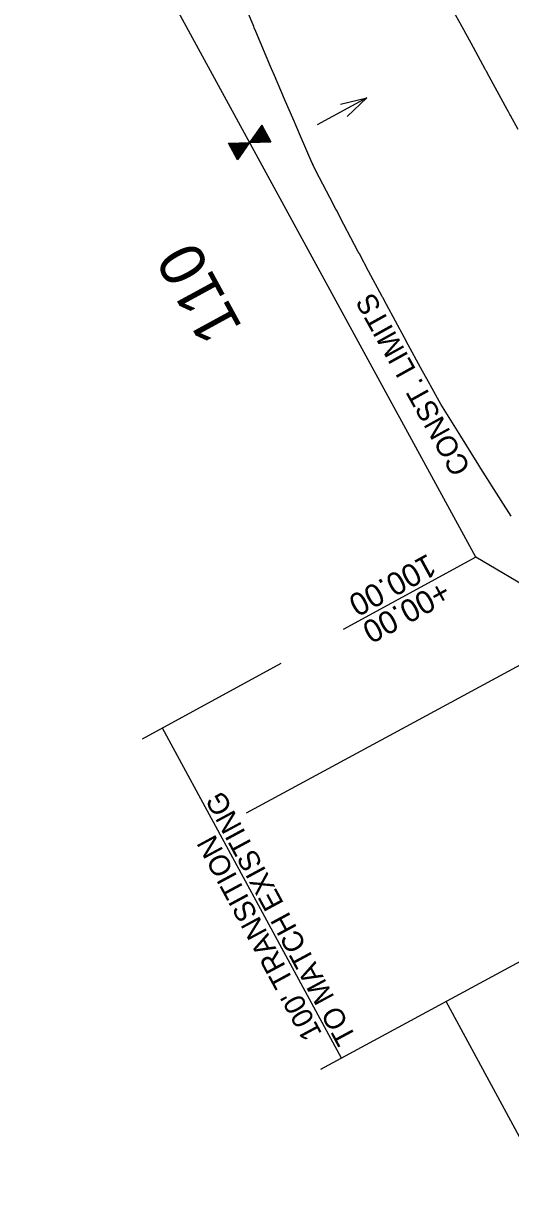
# Model space of a CAD drawing. Extents: x 1627557 to 1636561, y 783843 to 794002.
# Drawn here: x 1628014.2 to 1628143.1, y 784399.8 to 784710.3 of the extents above; entities that cross this region are included whole.
import ezdxf

# ---------------------------------------------------------------- set-up
doc = ezdxf.new("R2010")
doc.units = 0
for name, color, linetype in [('Flow Arrows', 7, 'Continuous'), ('GATE', 7, 'Continuous'), ('R_Clearzone', 7, 'Continuous'), ('R_Ditch', 7, 'Continuous'), ('R_Horz Alg Annot', 7, 'Continuous'), ('R_Proposed Const Limits', 7, 'Continuous'), ('R_Proposed Const Limits Annot', 7, 'Continuous'), ('R_ROW', 7, 'Continuous'), ('R_ROW Annot', 7, 'Continuous'), ('Transition Dimensions', 7, 'Continuous')]:
    doc.layers.add(name, color=color, linetype=linetype)

msp = doc.modelspace()

# ---------------------------------------------------------------- linework, layer by layer
at = {"layer": 'Flow Arrows'}
msp.add_line((1628105.06, 784690.6), (1628091.89, 784683.42), dxfattribs=at)
msp.add_lwpolyline([(1628098.06, 784688.91), (1628105.06, 784690.6), (1628099.84, 784685.63)], dxfattribs=at)
at = {"layer": 'GATE'}
for p, q in [((1628076.28, 784681.97), (1628077.95, 784678.91)), ((1628076.35, 784682.06), (1628078.06, 784678.91)), ((1628076.41, 784682.15), (1628078.17, 784678.92)), ((1628076.47, 784682.24), (1628078.29, 784678.92)), ((1628076.54, 784682.34), (1628078.4, 784678.92)), ((1628076.6, 784682.43), (1628078.51, 784678.93)), ((1628076.66, 784682.52), (1628078.62, 784678.93)), ((1628076.73, 784682.61), (1628078.73, 784678.94)), ((1628076.79, 784682.7), (1628078.84, 784678.94)), ((1628076.86, 784682.8), (1628078.96, 784678.94)), ((1628076.92, 784682.89), (1628079.07, 784678.95)), ((1628076.98, 784682.98), (1628079.18, 784678.95)), ((1628077.05, 784683.07), (1628079.29, 784678.96)), ((1628077.11, 784683.16), (1628079.4, 784678.96)), ((1628077.18, 784683.25), (1628079.51, 784678.96)), ((1628077.24, 784683.35), (1628079.63, 784678.97)), ((1628074.11, 784678.85), (1628074.15, 784678.77)), ((1628074.17, 784678.94), (1628074.26, 784678.78)), ((1628074.24, 784679.03), (1628074.38, 784678.78)), ((1628074.3, 784679.12), (1628074.49, 784678.79)), ((1628074.37, 784679.22), (1628074.6, 784678.79)), ((1628074.43, 784679.31), (1628074.71, 784678.79)), ((1628074.49, 784679.4), (1628074.82, 784678.8)), ((1628074.56, 784679.49), (1628074.93, 784678.8)), ((1628074.62, 784679.58), (1628075.05, 784678.81)), ((1628074.69, 784679.68), (1628075.16, 784678.81)), ((1628074.75, 784679.77), (1628075.27, 784678.81)), ((1628074.81, 784679.86), (1628075.38, 784678.82)), ((1628074.88, 784679.95), (1628075.49, 784678.82)), ((1628074.94, 784680.04), (1628075.6, 784678.83)), ((1628075, 784680.13), (1628075.72, 784678.83)), ((1628075.07, 784680.23), (1628075.83, 784678.83)), ((1628075.13, 784680.32), (1628075.94, 784678.84)), ((1628075.2, 784680.41), (1628076.05, 784678.84)), ((1628075.26, 784680.5), (1628076.16, 784678.85)), ((1628075.32, 784680.59), (1628076.27, 784678.85)), ((1628075.39, 784680.68), (1628076.39, 784678.85)), ((1628075.45, 784680.78), (1628076.5, 784678.86)), ((1628075.52, 784680.87), (1628076.61, 784678.86)), ((1628075.58, 784680.96), (1628076.72, 784678.87)), ((1628075.64, 784681.05), (1628076.83, 784678.87)), ((1628075.71, 784681.14), (1628076.94, 784678.87)), ((1628075.77, 784681.24), (1628077.06, 784678.88)), ((1628075.83, 784681.33), (1628077.17, 784678.88)), ((1628075.9, 784681.42), (1628077.28, 784678.89)), ((1628075.96, 784681.51), (1628077.39, 784678.89)), ((1628076.03, 784681.6), (1628077.5, 784678.89)), ((1628076.09, 784681.69), (1628077.62, 784678.9)), ((1628076.15, 784681.79), (1628077.73, 784678.9)), ((1628076.22, 784681.88), (1628077.84, 784678.9)), ((1628068.55, 784678.57), (1628070.91, 784674.25)), ((1628068.66, 784678.58), (1628070.97, 784674.34)), ((1628068.77, 784678.58), (1628071.04, 784674.43)), ((1628068.88, 784678.59), (1628071.1, 784674.52)), ((1628069, 784678.59), (1628071.16, 784674.61)), ((1628069.11, 784678.59), (1628071.23, 784674.71)), ((1628069.22, 784678.6), (1628071.29, 784674.8)), ((1628069.33, 784678.6), (1628071.36, 784674.89)), ((1628069.44, 784678.61), (1628071.42, 784674.98)), ((1628069.55, 784678.61), (1628071.48, 784675.07)), ((1628069.67, 784678.61), (1628071.55, 784675.17)), ((1628069.78, 784678.62), (1628071.61, 784675.26)), ((1628069.89, 784678.62), (1628071.67, 784675.35)), ((1628070, 784678.63), (1628071.74, 784675.44)), ((1628070.11, 784678.63), (1628071.8, 784675.53)), ((1628070.22, 784678.63), (1628071.87, 784675.62)), ((1628070.34, 784678.64), (1628071.93, 784675.72)), ((1628070.45, 784678.64), (1628071.99, 784675.81)), ((1628070.56, 784678.65), (1628072.06, 784675.9)), ((1628070.67, 784678.65), (1628072.12, 784675.99)), ((1628070.78, 784678.65), (1628072.19, 784676.08)), ((1628070.9, 784678.66), (1628072.25, 784676.17)), ((1628071.01, 784678.66), (1628072.31, 784676.27)), ((1628071.12, 784678.67), (1628072.38, 784676.36)), ((1628071.23, 784678.67), (1628072.44, 784676.45)), ((1628071.34, 784678.67), (1628072.5, 784676.54)), ((1628071.45, 784678.68), (1628072.57, 784676.63)), ((1628071.57, 784678.68), (1628072.63, 784676.73)), ((1628071.68, 784678.69), (1628072.7, 784676.82)), ((1628071.79, 784678.69), (1628072.76, 784676.91)), ((1628071.9, 784678.69), (1628072.82, 784677)), ((1628072.01, 784678.7), (1628072.89, 784677.09)), ((1628072.12, 784678.7), (1628072.95, 784677.18)), ((1628072.24, 784678.71), (1628073.02, 784677.28)), ((1628072.35, 784678.71), (1628073.08, 784677.37)), ((1628072.46, 784678.71), (1628073.14, 784677.46)), ((1628072.57, 784678.72), (1628073.21, 784677.55)), ((1628072.68, 784678.72), (1628073.27, 784677.64)), ((1628072.79, 784678.73), (1628073.34, 784677.73)), ((1628072.91, 784678.73), (1628073.4, 784677.83)), ((1628073.02, 784678.73), (1628073.46, 784677.92)), ((1628073.13, 784678.74), (1628073.53, 784678.01)), ((1628073.24, 784678.74), (1628073.59, 784678.1)), ((1628073.35, 784678.75), (1628073.65, 784678.19)), ((1628073.47, 784678.75), (1628073.72, 784678.29)), ((1628073.58, 784678.75), (1628073.78, 784678.38)), ((1628073.69, 784678.76), (1628073.85, 784678.47)), ((1628073.8, 784678.76), (1628073.91, 784678.56)), ((1628073.91, 784678.77), (1628073.97, 784678.65)), ((1628074.02, 784678.77), (1628074.04, 784678.74))]:
    msp.add_line(p, q, dxfattribs=at)
for points in [[(1628077.25, 784683.36), (1628074.06, 784678.77), (1628079.64, 784678.97)], [(1628068.47, 784678.57), (1628074.06, 784678.77), (1628070.86, 784674.18)]]:
    msp.add_lwpolyline(points, close=True, dxfattribs=at)
at = {"layer": 'R_Clearzone'}
msp.add_lwpolyline([(1628145.09, 784682.19), (1628143.05, 784685.93), (1628142.9, 784686.19), (1628142.55, 784686.85), (1628142.21, 784687.46), (1628137.43, 784696.24), (1628136.63, 784697.7), (1628136.58, 784697.8), (1628136.35, 784698.21), (1628132.64, 784705.02), (1628130.25, 784709.4), (1628130.21, 784709.47), (1628130.16, 784709.57), (1628127.85, 784713.8)], dxfattribs=at)
at = {"layer": 'R_Ditch'}
msp.add_lwpolyline([(1628145.09, 784682.19), (1628143.05, 784685.93), (1628142.9, 784686.19), (1628142.55, 784686.85), (1628142.21, 784687.46), (1628137.43, 784696.24), (1628136.63, 784697.7), (1628136.58, 784697.8), (1628136.35, 784698.21), (1628132.64, 784705.02), (1628130.25, 784709.4), (1628130.21, 784709.47), (1628130.16, 784709.57), (1628127.85, 784713.8)], dxfattribs=at)
at = {"layer": 'R_Horz Alg Annot'}
msp.add_lwpolyline([(1628236.53, 784589.68), (1628073.18, 784501.32)], dxfattribs=at)
at = {"layer": 'R_Proposed Const Limits'}
msp.add_lwpolyline([(1628143.29, 784579.84), (1628140.59, 784584.07), (1628135.23, 784592.53), (1628134.44, 784593.78), (1628134.39, 784593.86), (1628134.23, 784594.12), (1628129.9, 784601.01), (1628124.63, 784609.53), (1628121.94, 784614.42), (1628121.8, 784614.66), (1628121.74, 784614.79), (1628119.81, 784618.29), (1628115.49, 784626.21), (1628115.48, 784626.22), (1628115.47, 784626.25), (1628115.02, 784627.07), (1628110.27, 784635.87), (1628109.26, 784637.74), (1628109.22, 784637.81), (1628109.11, 784638.02), (1628105.54, 784644.69), (1628103.11, 784649.27), (1628103.02, 784649.44), (1628102.79, 784649.87), (1628100.86, 784653.52), (1628098.99, 784657.06), (1628097.01, 784660.83), (1628096.87, 784661.09), (1628096.52, 784661.76), (1628096.2, 784662.37), (1628091.6, 784671.25), (1628090.87, 784672.75), (1628090.82, 784672.85), (1628090.61, 784673.27), (1628087.53, 784680.42), (1628085.54, 784685.02), (1628085.5, 784685.1), (1628085.46, 784685.2), (1628083.54, 784689.64), (1628080.33, 784697.15), (1628080.3, 784697.22), (1628080.2, 784697.47), (1628079.6, 784698.88), (1628075.7, 784708.14), (1628075.28, 784709.13), (1628075.15, 784709.46), (1628074.97, 784709.89), (1628073.76, 784712.78)], dxfattribs=at)
at = {"layer": 'R_ROW'}
for p, q in [((1628133.89, 784569.02), (1628014.22, 784788.52)), ((1628234.18, 784509.96), (1628133.89, 784569.02))]:
    msp.add_line(p, q, dxfattribs=at)
at = {"layer": 'R_ROW Annot'}
msp.add_lwpolyline([(1628133.89, 784569.02), (1628098.77, 784549.88)], dxfattribs=at)
at = {"layer": 'Transition Dimensions'}
for p, q in [((1628082.31, 784540.87), (1628045.63, 784520.87)), ((1628098.37, 784436.48), (1628051.01, 784523.81)), ((1628228.66, 784506.97), (1628092.78, 784433.46)), ((1628197.81, 784319.04), (1628126.01, 784451.44))]:
    msp.add_line(p, q, dxfattribs=at)

# ---------------------------------------------------------------- texts
at = {"layer": 'R_Horz Alg Annot'}
msp.add_text('110', height=12, rotation=118.601, dxfattribs=at).set_placement((1628072.28, 784629.81))
at = {"layer": 'R_Proposed Const Limits Annot'}
msp.add_text('CONST. LIMITS', height=5.5, rotation=119.0505, dxfattribs=at).set_placement((1628132.67, 784592.58))
at = {"layer": 'R_ROW Annot'}
for s, p in [('100.00', (1628121.24, 784570.1)), ('+00.00', (1628125.07, 784563.08))]:
    msp.add_text(s, height=6, rotation=208.601, dxfattribs=at).set_placement(p)
at = {"layer": 'Transition Dimensions'}
for s, p in [('TO MATCH EXISTING', (1628102.43, 784441.78)), ("100' TRANSITION", (1628093.32, 784442.97))]:
    msp.add_text(s, height=5.5, rotation=118.3581, dxfattribs=at).set_placement(p)

doc.saveas('drawing.dxf')
